Omron CX-Programmer project 新工程 (CX-Programmer 6.10)

# PLC 新PLC1: CPM2* 

## Program 新程序1 (no task)

### Section 段1

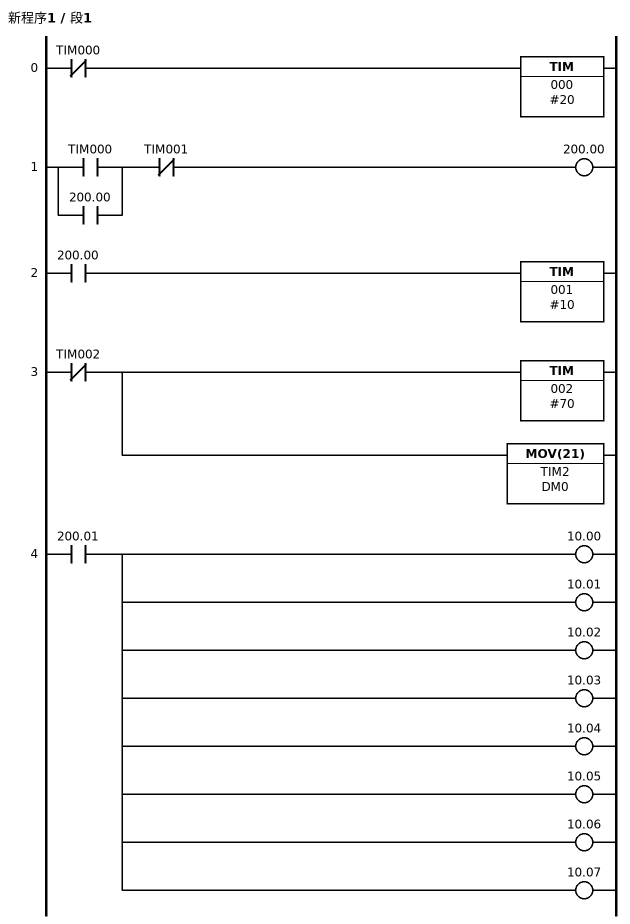
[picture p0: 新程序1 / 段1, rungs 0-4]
; rung 0
LDNOT TIM000
TIM 000 #20
; rung 1
LD TIM000
OR 200.00
ANDNOT TIM001
OUT 200.00
; rung 2
LD 200.00
TIM 001 #10
; rung 3
LDNOT TIM002
TIM 002 #70
MOV(21) TIM2 DM0
; rung 4
LD 200.01
OUT 10.00
OUT 10.01
OUT 10.02
OUT 10.03
OUT 10.04
OUT 10.05
OUT 10.06
OUT 10.07
; rung 5
END(01)

### Section 段2
; rung 0
END(01)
